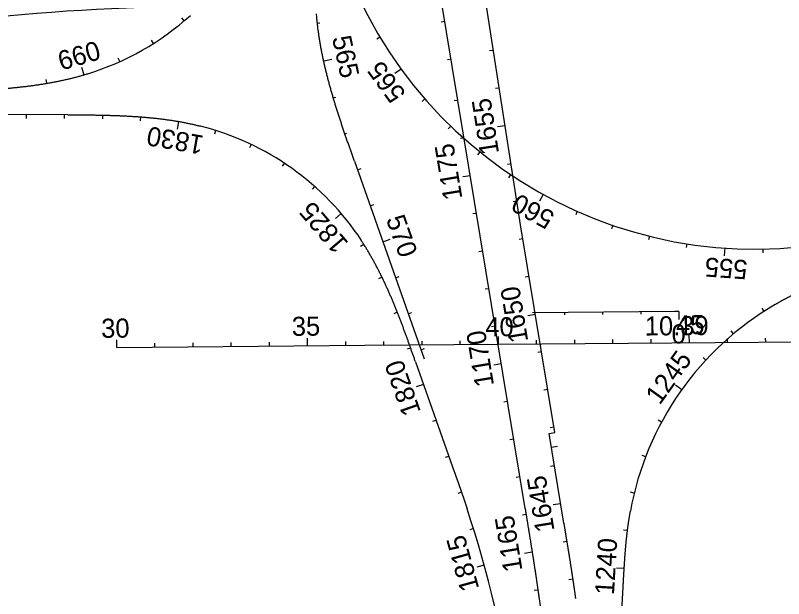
# Model space of a CAD drawing. Extents: x 448091 to 665917, y 1461380 to 1587607.
# Drawn here: x 475956 to 477968, y 1530300 to 1531828 of the extents above; entities that cross this region are included whole.
import ezdxf

# ---------------------------------------------------------------- set-up
doc = ezdxf.new("R2010")
doc.units = 0
for name, color, linetype in [('ATVHP', 7, 'Continuous'), ('BoxCulvert_ep', 7, 'Continuous'), ('TextShtNo', 7, 'Continuous'), ('TextTitle', 7, 'Continuous')]:
    doc.layers.add(name, color=color, linetype=linetype)

msp = doc.modelspace()

# ---------------------------------------------------------------- linework, layer by layer
at = {"layer": 'ATVHP'}
for p, q in [((477683.3, 1531051.7), (477310.1, 1531048.6)), ((477393.7, 1531049.3), (477393.7, 1531043.6)), ((477493.7, 1531050.1), (477493.7, 1531044.4)), ((477593.7, 1531051), (477593.7, 1531045.2)), ((477693.6, 1531051.8), (477683.3, 1531051.7)), ((477693.6, 1531051.8), (477693.8, 1531031.1))]:
    msp.add_line(p, q, dxfattribs=at)
at = {"layer": 'BoxCulvert_ep'}
for p, q in [((477221.1, 1530966.4), (482148.1, 1531007.3)), ((476221.1, 1530958.1), (476220.9, 1530978.1)), ((476721.1, 1530962.2), (476720.9, 1530982.2)), ((476921.1, 1530963.9), (476921, 1530973.9)), ((477021.1, 1530964.7), (477021, 1530974.7)), ((477121.1, 1530965.5), (477121, 1530975.5)), ((477221.1, 1530966.4), (477220.9, 1530986.4)), ((477321.1, 1530967.2), (477321, 1530977.2)), ((477421.1, 1530968), (477421, 1530978)), ((477521.1, 1530968.9), (477521, 1530978.9)), ((477621.1, 1530969.7), (477621, 1530979.7)), ((477721.1, 1530970.5), (477720.9, 1530990.5)), ((477821.1, 1530971.4), (477821, 1530981.4)), ((477921.1, 1530972.2), (477921, 1530982.2)), ((476221.1, 1530958.1), (476871, 1530963.5)), ((476321.1, 1530958.9), (476321, 1530968.9)), ((476421.1, 1530959.7), (476421, 1530969.7)), ((476521.1, 1530960.6), (476521, 1530970.6)), ((476621.1, 1530961.4), (476621, 1530971.4)), ((476821.1, 1530963.1), (476821, 1530973.1)), ((476871, 1530963.5), (477221.1, 1530966.4))]:
    msp.add_line(p, q, dxfattribs=at)
at = {"layer": 'TextShtNo'}
for p, q in [((477290.8, 1530535.8), (476693, 1534170.8)), ((476843.9, 1531445.6), (477026.5, 1530928.1)), ((477368.5, 1530734.9), (477279.1, 1531278.8)), ((477106.4, 1530629.5), (477004.2, 1530919.1)), ((477353.7, 1530732.5), (477368.5, 1530734.9)), ((477392.4, 1530497.3), (477353.7, 1530732.5)), ((477532.6, 1530046.1), (477547.7, 1530329.9))]:
    msp.add_line(p, q, dxfattribs=at)
for centre, radius, start, end in [((477892.9, 1532361.8), 1146.2, 190.8482, 279.0283), ((476476.9, 1526122.2), 5729.6, 90.3311, 102.9478), ((478344.2, 1530387.7), 790.3, 120.2271, 169.7108), ((474422.2, 1529629.3), 2863.6, 357.4315, 18.435)]:
    msp.add_arc(centre, radius, start, end, dxfattribs=at)
for points in [[(477003.9, 1530920.1), (477002.3, 1530924.5), (477000.7, 1530929), (476999.2, 1530933.4), (476997.6, 1530937.9), (476996, 1530942.4), (476994.4, 1530946.8), (476992.8, 1530951.3), (476991.3, 1530955.7), (476989.7, 1530960.2), (476988.1, 1530964.6), (476986.5, 1530969.1), (476984.9, 1530973.5), (476983.3, 1530978), (476981.7, 1530982.4), (476980, 1530986.9), (476978.4, 1530991.3), (476976.8, 1530995.8), (476975.2, 1531000.2), (476973.5, 1531004.6), (476971.9, 1531009.1), (476970.2, 1531013.5), (476968.5, 1531017.9), (476966.9, 1531022.4), (476965.2, 1531026.8), (476963.5, 1531031.2), (476961.8, 1531035.6), (476960.1, 1531040), (476958.4, 1531044.4), (476956.6, 1531048.8), (476954.9, 1531053.2), (476953.1, 1531057.6), (476951.4, 1531062), (476949.6, 1531066.4), (476947.8, 1531070.8), (476946, 1531075.1), (476944.1, 1531079.5), (476942.3, 1531083.8), (476940.5, 1531088.2), (476938.6, 1531092.5), (476936.7, 1531096.9), (476934.8, 1531101.2), (476932.9, 1531105.5), (476931, 1531109.9), (476929, 1531114.2), (476927.1, 1531118.5), (476925.1, 1531122.8), (476923.1, 1531127.1), (476921.1, 1531131.3), (476919.1, 1531135.6), (476917, 1531139.9), (476914.9, 1531144.1), (476912.8, 1531148.4), (476910.7, 1531152.6), (476908.6, 1531156.8), (476906.5, 1531161), (476904.3, 1531165.2), (476902.1, 1531169.4), (476899.9, 1531173.6), (476897.6, 1531177.8), (476895.4, 1531181.9), (476893.1, 1531186.1), (476890.8, 1531190.2), (476888.5, 1531194.3), (476886.1, 1531198.4), (476883.8, 1531202.5), (476881.4, 1531206.6), (476879, 1531210.7), (476876.5, 1531214.7), (476874.1, 1531218.8), (476871.6, 1531222.8), (476869, 1531226.8), (476866.5, 1531230.8), (476863.9, 1531234.8), (476861.3, 1531238.7)], [(478126.9, 1531156.3), (478124.4, 1531155.2), (478122, 1531154.2), (478119.5, 1531153.1), (478117, 1531152.1), (478114.5, 1531151), (478112, 1531149.9), (478109.5, 1531148.9), (478107, 1531147.8), (478104.5, 1531146.8), (478102.1, 1531145.7), (478099.6, 1531144.6), (478097.1, 1531143.6), (478094.6, 1531142.5), (478092.1, 1531141.4), (478089.6, 1531140.4), (478087.2, 1531139.3), (478084.7, 1531138.2), (478082.2, 1531137.2), (478079.7, 1531136.1), (478077.2, 1531135), (478074.8, 1531133.9), (478072.3, 1531132.9), (478069.8, 1531131.8), (478067.3, 1531130.7), (478064.9, 1531129.6), (478062.4, 1531128.5), (478059.9, 1531127.4), (478057.4, 1531126.3), (478055, 1531125.2), (478052.5, 1531124.1), (478050, 1531123), (478047.6, 1531121.9), (478045.1, 1531120.8), (478042.7, 1531119.7), (478040.2, 1531118.5), (478037.7, 1531117.4), (478035.3, 1531116.3), (478032.8, 1531115.1), (478030.4, 1531114), (478027.9, 1531112.9), (478025.5, 1531111.7), (478023, 1531110.5), (478020.6, 1531109.4), (478018.2, 1531108.2), (478015.7, 1531107.1), (478013.3, 1531105.9), (478010.9, 1531104.7), (478008.4, 1531103.5), (478006, 1531102.3), (478003.6, 1531101.1), (478001.2, 1531099.9), (477998.7, 1531098.7), (477996.3, 1531097.5), (477993.9, 1531096.3), (477991.5, 1531095.1), (477989.1, 1531093.9), (477986.7, 1531092.6), (477984.3, 1531091.4), (477981.9, 1531090.1), (477979.5, 1531088.9), (477977.1, 1531087.6), (477974.7, 1531086.3), (477972.3, 1531085.1), (477970, 1531083.8), (477967.6, 1531082.5), (477965.2, 1531081.2), (477962.8, 1531079.9), (477960.5, 1531078.6), (477958.1, 1531077.3), (477955.8, 1531075.9), (477953.4, 1531074.6), (477951.1, 1531073.3), (477948.7, 1531071.9), (477946.4, 1531070.6)], [(477106.4, 1530629.5), (477106.8, 1530628.2), (477107.3, 1530626.9), (477107.7, 1530625.6), (477108.2, 1530624.4), (477108.6, 1530623.1), (477109.1, 1530621.8), (477109.5, 1530620.5), (477110, 1530619.3), (477110.4, 1530618), (477110.9, 1530616.7), (477111.3, 1530615.4), (477111.8, 1530614.2), (477112.2, 1530612.9), (477112.7, 1530611.6), (477113.1, 1530610.3), (477113.6, 1530609.1), (477114, 1530607.8), (477114.5, 1530606.5), (477114.9, 1530605.2), (477115.4, 1530604), (477115.8, 1530602.7), (477116.3, 1530601.4), (477116.7, 1530600.1), (477117.2, 1530598.9), (477117.6, 1530597.6), (477118.1, 1530596.3), (477118.5, 1530595), (477119, 1530593.8), (477119.4, 1530592.5), (477119.8, 1530591.2), (477120.3, 1530589.9), (477120.7, 1530588.7), (477121.2, 1530587.4), (477121.6, 1530586.1), (477122.1, 1530584.8), (477122.5, 1530583.6), (477123, 1530582.3), (477123.4, 1530581), (477123.8, 1530579.7), (477124.3, 1530578.5), (477124.7, 1530577.2), (477125.2, 1530575.9), (477125.6, 1530574.6), (477126.1, 1530573.4), (477126.5, 1530572.1), (477126.9, 1530570.8), (477127.4, 1530569.5), (477127.8, 1530568.2), (477128.3, 1530567), (477128.7, 1530565.7), (477129.1, 1530564.4), (477129.6, 1530563.1), (477130, 1530561.9), (477130.5, 1530560.6), (477130.9, 1530559.3), (477131.3, 1530558), (477131.8, 1530556.7), (477132.2, 1530555.5), (477132.6, 1530554.2), (477133.1, 1530552.9), (477133.5, 1530551.6), (477133.9, 1530550.3), (477134.4, 1530549.1), (477134.8, 1530547.8), (477135.2, 1530546.5), (477135.7, 1530545.2), (477136.1, 1530544), (477136.5, 1530542.7), (477137, 1530541.4), (477137.4, 1530540.1), (477137.8, 1530538.8), (477138.3, 1530537.5), (477138.7, 1530536.3), (477139.1, 1530535)], [(477290.8, 1530535.8), (477291.5, 1530531.8), (477292.1, 1530527.8), (477292.8, 1530523.8), (477293.5, 1530519.8), (477294.1, 1530515.8), (477294.8, 1530511.8), (477295.4, 1530507.8), (477296.1, 1530503.8), (477296.7, 1530499.8), (477297.4, 1530495.8), (477298.1, 1530491.8), (477298.7, 1530487.8), (477299.4, 1530483.8), (477300, 1530479.8), (477300.7, 1530475.8), (477301.3, 1530471.8), (477302, 1530467.7), (477302.6, 1530463.7), (477303.3, 1530459.7), (477303.9, 1530455.7), (477304.6, 1530451.7), (477305.2, 1530447.7), (477305.8, 1530443.7), (477306.5, 1530439.7), (477307.1, 1530435.7), (477307.8, 1530431.7), (477308.4, 1530427.7), (477309, 1530423.7), (477309.7, 1530419.7), (477310.3, 1530415.7), (477310.9, 1530411.7), (477311.6, 1530407.7), (477312.2, 1530403.7), (477312.8, 1530399.7), (477313.4, 1530395.7), (477314.1, 1530391.7), (477314.7, 1530387.7), (477315.3, 1530383.7), (477315.9, 1530379.7), (477316.5, 1530375.7), (477317.1, 1530371.6), (477317.8, 1530367.6), (477318.4, 1530363.6), (477319, 1530359.6), (477319.6, 1530355.6), (477320.2, 1530351.6), (477320.8, 1530347.6), (477321.4, 1530343.6), (477321.9, 1530339.6), (477322.5, 1530335.6), (477323.1, 1530331.5), (477323.7, 1530327.5), (477324.3, 1530323.5), (477324.9, 1530319.5), (477325.4, 1530315.5), (477326, 1530311.5), (477326.6, 1530307.5), (477327.1, 1530303.4), (477327.7, 1530299.4), (477328.2, 1530295.4), (477328.8, 1530291.4), (477329.3, 1530287.4), (477329.9, 1530283.4), (477330.4, 1530279.4), (477331, 1530275.3), (477331.5, 1530271.3), (477332, 1530267.3), (477332.6, 1530263.3), (477333.1, 1530259.3), (477333.6, 1530255.2), (477334.1, 1530251.2), (477334.6, 1530247.2), (477335.1, 1530243.2), (477335.6, 1530239.1)], [(477547.7, 1530329.9), (477547.8, 1530332.6), (477548, 1530335.3), (477548.1, 1530338), (477548.2, 1530340.7), (477548.4, 1530343.4), (477548.5, 1530346.1), (477548.7, 1530348.8), (477548.8, 1530351.5), (477549, 1530354.2), (477549.1, 1530356.9), (477549.3, 1530359.6), (477549.4, 1530362.3), (477549.6, 1530365), (477549.7, 1530367.7), (477549.9, 1530370.4), (477550, 1530373.1), (477550.2, 1530375.8), (477550.4, 1530378.5), (477550.5, 1530381.2), (477550.7, 1530383.9), (477550.9, 1530386.6), (477551, 1530389.3), (477551.2, 1530392), (477551.4, 1530394.7), (477551.6, 1530397.4), (477551.8, 1530400.1), (477551.9, 1530402.8), (477552.1, 1530405.5), (477552.3, 1530408.2), (477552.5, 1530410.9), (477552.7, 1530413.6), (477552.9, 1530416.3), (477553.1, 1530419), (477553.4, 1530421.6), (477553.6, 1530424.3), (477553.8, 1530427), (477554, 1530429.7), (477554.2, 1530432.4), (477554.5, 1530435.1), (477554.7, 1530437.8), (477555, 1530440.5), (477555.2, 1530443.2), (477555.5, 1530445.9), (477555.7, 1530448.6), (477556, 1530451.3), (477556.3, 1530453.9), (477556.6, 1530456.6), (477556.8, 1530459.3), (477557.1, 1530462), (477557.4, 1530464.7), (477557.7, 1530467.4), (477558, 1530470.1), (477558.3, 1530472.8), (477558.7, 1530475.4), (477559, 1530478.1), (477559.3, 1530480.8), (477559.7, 1530483.5), (477560, 1530486.2), (477560.4, 1530488.8), (477560.7, 1530491.5), (477561.1, 1530494.2), (477561.5, 1530496.9), (477561.9, 1530499.5), (477562.3, 1530502.2), (477562.7, 1530504.9), (477563.1, 1530507.6), (477563.5, 1530510.2), (477563.9, 1530512.9), (477564.4, 1530515.6), (477564.8, 1530518.2), (477565.3, 1530520.9), (477565.7, 1530523.6), (477566.2, 1530526.2), (477566.7, 1530528.9)]]:
    msp.add_spline(points, degree=3, dxfattribs=at)
at = {"layer": 'TextTitle'}
for p, q in [((477279.1, 1531278.8), (477141.3, 1532164.1)), ((476397.7, 1531813.7), (476391.2, 1531821.3)), ((476747.8, 1531807.8), (476753.5, 1531808.5)), ((476747.8, 1531807.8), (476752.1, 1531808.3)), ((477080.9, 1531812.1), (477071, 1531810.5)), ((476317.2, 1531754.5), (476311.9, 1531762.9)), ((476911.1, 1531770.9), (476902.3, 1531765.5)), ((477207.9, 1531736.3), (477198, 1531734.8)), ((476229.3, 1531707), (476225.1, 1531716.1)), ((476764.1, 1531709.2), (476784.3, 1531713.6)), ((476764.1, 1531709.2), (476768.3, 1531710.1)), ((477097.1, 1531713.4), (477087.3, 1531711.8)), ((476135.6, 1531672.3), (476130, 1531691.5)), ((476966.3, 1531687.5), (476949.9, 1531675.6)), ((476038.1, 1531650), (476036.5, 1531659.9)), ((477223.3, 1531637.5), (477213.4, 1531636)), ((476789.2, 1531612.4), (476794.7, 1531614.1)), ((476789.2, 1531612.4), (476793.3, 1531613.7)), ((477028.6, 1531609.3), (477020.9, 1531602.6)), ((477114.9, 1531605.3), (477105, 1531603.7)), ((476093.2, 1531567.5), (475668.2, 1531569.2)), ((475983.7, 1531567.9), (475983.7, 1531557.9)), ((476083.7, 1531567.5), (476083.7, 1531557.5)), ((476183.7, 1531566.6), (476183.5, 1531556.6)), ((476283.6, 1531562.1), (476282.8, 1531552.1)), ((476382.8, 1531550), (476379.4, 1531530.3)), ((477096.3, 1531537.5), (477089.4, 1531530.4)), ((477238.6, 1531538.7), (477218.9, 1531535.6)), ((476480, 1531526.6), (476477, 1531517)), ((476818.6, 1531517.9), (476824.1, 1531519.8)), ((477131.1, 1531506.6), (477121.3, 1531505)), ((476572.9, 1531490), (476568.6, 1531481)), ((477172.4, 1531470.7), (477165.9, 1531462.7)), ((476659.9, 1531440.8), (476654.4, 1531432.5)), ((477254.1, 1531439.1), (477244.3, 1531437.6)), ((476851.7, 1531423.5), (476861.1, 1531426.8)), ((477147.4, 1531407.9), (477127.6, 1531404.7)), ((477252.8, 1531411.3), (477247.1, 1531402.7)), ((476739.2, 1531380), (476732.6, 1531372.5)), ((477338.1, 1531359.1), (477328.3, 1531341.4)), ((477269.4, 1531341.1), (477259.5, 1531339.6)), ((476885, 1531329.2), (476894.4, 1531332.5)), ((476809.3, 1531308.8), (476794.1, 1531295.8)), ((477163.6, 1531309.3), (477153.7, 1531307.7)), ((477427.6, 1531314.6), (477423.4, 1531305.2)), ((477520.6, 1531278), (477517.3, 1531268.3)), ((476918.2, 1531234.9), (476937.1, 1531241.6)), ((477285.1, 1531242.3), (477275.2, 1531240.7)), ((477616.5, 1531249.7), (477614, 1531239.7)), ((476868.2, 1531228.1), (476859.8, 1531222.8)), ((477714.5, 1531229.8), (477712.9, 1531219.6)), ((477813.8, 1531218.6), (477812.4, 1531198.3)), ((477913.7, 1531216), (477913.9, 1531205.7)), ((477179.5, 1531210.4), (477170, 1531208.8)), ((476916.1, 1531141.7), (476907.1, 1531137.4)), ((476951.5, 1531140.6), (476960.9, 1531143.9)), ((477301.3, 1531143.7), (477291.4, 1531142)), ((477196.1, 1531111.9), (477186.2, 1531110.3)), ((477917.3, 1531052.8), (477911.9, 1531061.2)), ((476956.1, 1531050.1), (476946.8, 1531046.4)), ((476984.8, 1531046.3), (476994.2, 1531049.6)), ((477317.7, 1531044.2), (477297.9, 1531040.9)), ((477212.3, 1531013.3), (477202.4, 1531011.6)), ((477836.8, 1530993.6), (477830.4, 1531001.2)), ((476991, 1530956.4), (476981.6, 1530953.1)), ((477018.1, 1530952), (477027.5, 1530955.3)), ((477333.8, 1530946.3), (477323.9, 1530944.7)), ((477228.5, 1530914.6), (477208.8, 1530911.3)), ((477764.4, 1530924.7), (477757, 1530931.5)), ((477024.6, 1530861.2), (477005.8, 1530854.5)), ((477701.3, 1530847.2), (477685, 1530858.8)), ((477350, 1530847.6), (477340.1, 1530846)), ((477244.8, 1530815.9), (477234.9, 1530814.3)), ((477057.9, 1530766.9), (477048.5, 1530763.6)), ((477648.4, 1530762.4), (477639.6, 1530767.1)), ((477366.2, 1530749), (477356.4, 1530747.3)), ((477261, 1530717.2), (477251.1, 1530715.6)), ((477359.7, 1530696.4), (477375.5, 1530699)), ((477091.2, 1530672.6), (477081.8, 1530669.3)), ((477606.7, 1530671.6), (477597.4, 1530675.2)), ((477367.7, 1530647.9), (477357.8, 1530646.2)), ((477277.2, 1530618.6), (477267.3, 1530616.9)), ((477124.4, 1530578.3), (477114.9, 1530575)), ((477576.8, 1530576.2), (477567.1, 1530578.6)), ((477384, 1530548.4), (477364.3, 1530545.1)), ((477293.4, 1530519.9), (477283.6, 1530518.3)), ((477155.5, 1530483.3), (477146, 1530480.3)), ((477559, 1530477.9), (477549, 1530479.1)), ((477400.1, 1530449.7), (477390.2, 1530448.1)), ((477309.4, 1530421.2), (477289.7, 1530418.3)), ((477183.6, 1530387.4), (477164.4, 1530382.1)), ((477550.3, 1530378.3), (477530.4, 1530379.5)), ((477415.6, 1530350.9), (477405.7, 1530349.4)), ((477324.3, 1530322.1), (477314.5, 1530320.9))]:
    msp.add_line(p, q, dxfattribs=at)
for centre, start, end in [((475934, 1532359.5), 287.1651, 312.0966), ((476264.8, 1530843.5), 33.435, 75.7649)]:
    msp.add_arc(centre, 716.2, start, end, dxfattribs=at)
for points in [[(476843.9, 1531445.6), (476842.1, 1531450.7), (476840.3, 1531455.8), (476838.5, 1531460.9), (476836.7, 1531466), (476834.9, 1531471.1), (476833.1, 1531476.2), (476831.3, 1531481.3), (476829.6, 1531486.4), (476827.8, 1531491.5), (476826, 1531496.6), (476824.2, 1531501.7), (476822.5, 1531506.8), (476820.7, 1531511.9), (476818.9, 1531517), (476817.2, 1531522.1), (476815.5, 1531527.3), (476813.7, 1531532.4), (476812, 1531537.5), (476810.3, 1531542.6), (476808.6, 1531547.8), (476806.9, 1531552.9), (476805.2, 1531558), (476803.5, 1531563.2), (476801.9, 1531568.3), (476800.2, 1531573.5), (476798.6, 1531578.6), (476796.9, 1531583.8), (476795.3, 1531588.9), (476793.7, 1531594.1), (476792.1, 1531599.3), (476790.6, 1531604.4), (476789, 1531609.6), (476787.5, 1531614.8), (476786, 1531620), (476784.5, 1531625.2), (476783, 1531630.4), (476781.5, 1531635.6), (476780, 1531640.8), (476778.6, 1531646), (476777.2, 1531651.2), (476775.8, 1531656.4), (476774.4, 1531661.6), (476773.1, 1531666.9), (476771.7, 1531672.1), (476770.4, 1531677.4), (476769.2, 1531682.6), (476767.9, 1531687.9), (476766.6, 1531693.1), (476765.4, 1531698.4), (476764.2, 1531703.7), (476763.1, 1531708.9), (476761.9, 1531714.2), (476760.8, 1531719.5), (476759.7, 1531724.8), (476758.7, 1531730.1), (476757.6, 1531735.4), (476756.6, 1531740.7), (476755.7, 1531746.1), (476754.7, 1531751.4), (476753.8, 1531756.7), (476752.9, 1531762), (476752.1, 1531767.4), (476751.3, 1531772.7), (476750.5, 1531778.1), (476749.7, 1531783.4), (476749, 1531788.8), (476748.3, 1531794.1), (476747.6, 1531799.5), (476747, 1531804.9), (476746.4, 1531810.2), (476745.9, 1531815.6), (476745.4, 1531821), (476744.9, 1531826.4), (476744.5, 1531831.8)], [(475789.5, 1531628), (475794.3, 1531628.2), (475799.2, 1531628.4), (475804.1, 1531628.7), (475808.9, 1531628.9), (475813.8, 1531629.1), (475818.6, 1531629.4), (475823.5, 1531629.6), (475828.3, 1531629.9), (475833.2, 1531630.1), (475838.1, 1531630.4), (475842.9, 1531630.6), (475847.8, 1531630.9), (475852.6, 1531631.2), (475857.5, 1531631.5), (475862.3, 1531631.7), (475867.2, 1531632), (475872.1, 1531632.3), (475876.9, 1531632.6), (475881.8, 1531632.9), (475886.6, 1531633.2), (475891.5, 1531633.6), (475896.3, 1531633.9), (475901.2, 1531634.3), (475906, 1531634.6), (475910.9, 1531635), (475915.7, 1531635.4), (475920.6, 1531635.8), (475925.4, 1531636.2), (475930.3, 1531636.6), (475935.1, 1531637), (475940, 1531637.4), (475944.8, 1531637.9), (475949.7, 1531638.4), (475954.5, 1531638.9), (475959.3, 1531639.4), (475964.2, 1531639.9), (475969, 1531640.4), (475973.8, 1531641), (475978.7, 1531641.5), (475983.5, 1531642.1), (475988.3, 1531642.7), (475993.2, 1531643.3), (475998, 1531644), (476002.8, 1531644.6), (476007.6, 1531645.3), (476012.4, 1531646), (476017.3, 1531646.7), (476022.1, 1531647.4), (476026.9, 1531648.2), (476031.7, 1531649), (476036.5, 1531649.8), (476041.3, 1531650.6), (476046.1, 1531651.4), (476050.8, 1531652.3), (476055.6, 1531653.2), (476060.4, 1531654.1), (476065.2, 1531655.1), (476069.9, 1531656), (476074.7, 1531657), (476079.5, 1531658), (476084.2, 1531659.1), (476089, 1531660.1), (476093.7, 1531661.2), (476098.4, 1531662.4), (476103.2, 1531663.5), (476107.9, 1531664.7), (476112.6, 1531665.9), (476117.3, 1531667.1), (476122, 1531668.4), (476126.7, 1531669.7), (476131.4, 1531671), (476136, 1531672.4), (476140.7, 1531673.8), (476145.3, 1531675.2)], [(476093.2, 1531567.5), (476097.9, 1531567.5), (476102.6, 1531567.4), (476107.3, 1531567.4), (476112.1, 1531567.4), (476116.8, 1531567.4), (476121.5, 1531567.4), (476126.3, 1531567.3), (476131, 1531567.3), (476135.7, 1531567.3), (476140.4, 1531567.2), (476145.2, 1531567.2), (476149.9, 1531567.1), (476154.6, 1531567.1), (476159.4, 1531567), (476164.1, 1531567), (476168.8, 1531566.9), (476173.6, 1531566.8), (476178.3, 1531566.7), (476183, 1531566.6), (476187.7, 1531566.5), (476192.5, 1531566.4), (476197.2, 1531566.3), (476201.9, 1531566.2), (476206.7, 1531566), (476211.4, 1531565.9), (476216.1, 1531565.7), (476220.8, 1531565.6), (476225.6, 1531565.4), (476230.3, 1531565.2), (476235, 1531565), (476239.7, 1531564.8), (476244.5, 1531564.6), (476249.2, 1531564.3), (476253.9, 1531564.1), (476258.6, 1531563.8), (476263.4, 1531563.5), (476268.1, 1531563.2), (476272.8, 1531562.9), (476277.5, 1531562.6), (476282.2, 1531562.2), (476286.9, 1531561.8), (476291.7, 1531561.5), (476296.4, 1531561.1), (476301.1, 1531560.6), (476305.8, 1531560.2), (476310.5, 1531559.7), (476315.2, 1531559.3), (476319.9, 1531558.8), (476324.6, 1531558.3), (476329.3, 1531557.7), (476334, 1531557.2), (476338.7, 1531556.6), (476343.4, 1531556), (476348.1, 1531555.4), (476352.8, 1531554.7), (476357.4, 1531554.1), (476362.1, 1531553.4), (476366.8, 1531552.7), (476371.5, 1531551.9), (476376.1, 1531551.2), (476380.8, 1531550.4), (476385.5, 1531549.6), (476390.1, 1531548.7), (476394.8, 1531547.8), (476399.4, 1531547), (476404.1, 1531546), (476408.7, 1531545.1), (476413.3, 1531544.1), (476417.9, 1531543.1), (476422.6, 1531542.1), (476427.2, 1531541), (476431.8, 1531539.9), (476436.4, 1531538.8), (476441, 1531537.7)], [(477392.3, 1530497.3), (477392.7, 1530494.7), (477393.1, 1530492), (477393.6, 1530489.3), (477394, 1530486.7), (477394.4, 1530484), (477394.9, 1530481.3), (477395.3, 1530478.7), (477395.8, 1530476), (477396.2, 1530473.3), (477396.6, 1530470.7), (477397.1, 1530468), (477397.5, 1530465.3), (477397.9, 1530462.7), (477398.4, 1530460), (477398.8, 1530457.3), (477399.3, 1530454.6), (477399.7, 1530452), (477400.1, 1530449.3), (477400.6, 1530446.6), (477401, 1530444), (477401.4, 1530441.3), (477401.9, 1530438.6), (477402.3, 1530436), (477402.7, 1530433.3), (477403.2, 1530430.6), (477403.6, 1530428), (477404, 1530425.3), (477404.4, 1530422.6), (477404.9, 1530420), (477405.3, 1530417.3), (477405.7, 1530414.6), (477406.1, 1530412), (477406.6, 1530409.3), (477407, 1530406.6), (477407.4, 1530404), (477407.8, 1530401.3), (477408.3, 1530398.6), (477408.7, 1530395.9), (477409.1, 1530393.3), (477409.5, 1530390.6), (477409.9, 1530387.9), (477410.4, 1530385.3), (477410.8, 1530382.6), (477411.2, 1530379.9), (477411.6, 1530377.3), (477412, 1530374.6), (477412.4, 1530371.9), (477412.8, 1530369.2), (477413.2, 1530366.6), (477413.6, 1530363.9), (477414.1, 1530361.2), (477414.5, 1530358.6), (477414.9, 1530355.9), (477415.3, 1530353.2), (477415.7, 1530350.5), (477416.1, 1530347.9), (477416.5, 1530345.2), (477416.9, 1530342.5), (477417.3, 1530339.9), (477417.6, 1530337.2), (477418, 1530334.5), (477418.4, 1530331.8), (477418.8, 1530329.2), (477419.2, 1530326.5), (477419.6, 1530323.8), (477420, 1530321.1), (477420.4, 1530318.5), (477420.7, 1530315.8), (477421.1, 1530313.1), (477421.5, 1530310.4), (477421.9, 1530307.8), (477422.2, 1530305.1), (477422.6, 1530302.4), (477423, 1530299.7)]]:
    msp.add_spline(points, degree=3, dxfattribs=at)

# ---------------------------------------------------------------- texts
at = {"layer": 'ATVHP'}
for s, rotation, p in [('10.39', 0.4798, (477604.6, 1530989.1)), ('0', 180.4797, (477711.5, 1531018.6))]:
    msp.add_text(s, height=50, rotation=rotation, dxfattribs=at).set_placement(p)
at = {"layer": 'BoxCulvert_ep'}
for s, rotation, p in [('30', 0.4761, (476180.5, 1530983.1)), ('35', 0.4761, (476679.9, 1530988.2)), ('40', 0.4761, (477186.7, 1530986.8)), ('45', 0.4764, (477686.3, 1530992.1))]:
    msp.add_text(s, height=50, rotation=rotation, dxfattribs=at).set_placement(p)
at = {"layer": 'TextTitle'}
for s, rotation, p in [('660', 16.3615, (476075.8, 1531683.1)), ('565', 282.2624, (476784.9, 1531769.3)), ('565', 126.0411, (476980.5, 1531622.9)), ('1655', 98.8441, (477222.8, 1531467)), ('1830', 170.1158, (476451.6, 1531512.1)), ('1175', 99.34, (477126.8, 1531348.5)), ('560', 151.0411, (477371.8, 1531309.1)), ('1825', 130.5195, (476830.3, 1531231.5)), ('570', 289.435, (476925.9, 1531294.6)), ('555', 176.0411, (477874.8, 1531186.1)), ('1650', 99.3401, (477299.2, 1530974.4)), ('1170', 99.34, (477209.7, 1530858.9)), ('1245', 54.4508, (477643.5, 1530805.1)), ('1820', 109.435, (477018.4, 1530789.4)), ('1645', 99.3401, (477368.2, 1530478.4)), ('1165', 99.34, (477284.2, 1530374)), ('1815', 105.3496, (477171, 1530326.6)), ('1240', 86.536, (477523.5, 1530308.4))]:
    msp.add_text(s, height=50, rotation=rotation, dxfattribs=at).set_placement(p)

doc.saveas('drawing.dxf')
